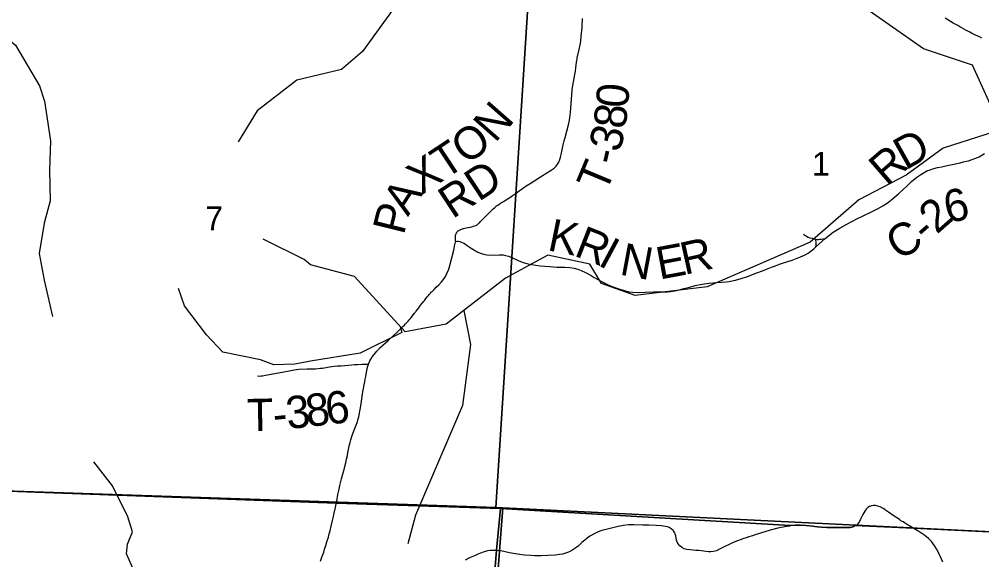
# Model space of a CAD drawing. Extents: x 0 to 34, y 0 to 22.
# Drawn here: x 4.109 to 5.797, y 15.893 to 16.841 of the extents above; entities that cross this region are included whole.
import ezdxf

# ---------------------------------------------------------------- set-up
doc = ezdxf.new("R2010")
doc.units = 0
for name, color, linetype in [('Default', 7, 'Continuous'), ('GM_X_County_Road', 7, 'Continuous'), ('GM_X_County_Road_Text', 7, 'Continuous'), ('GM_X_Minor_River', 7, 'Continuous'), ('GM_X_Section', 7, 'Continuous'), ('GM_X_Section_Text', 7, 'Continuous'), ('GM_X_Township_Road', 7, 'Continuous'), ('GM_X_Township_Road_Text', 7, 'Continuous')]:
    doc.layers.add(name, color=color, linetype=linetype)

msp = doc.modelspace()

# ---------------------------------------------------------------- linework, layer by layer
at = {"layer": 'Default'}
for points in [[(3.9292, 16.0191), (4.6644, 15.9921), (4.9525, 15.9829), (5.4606, 15.953), (5.4699, 15.9536), (5.4787, 15.9537), (5.4884, 15.9532), (5.5007, 15.9519), (5.5038, 15.9516), (5.5088, 15.951), (5.5156, 15.9503), (5.5249, 15.9499), (5.5387, 15.9494), (5.5476, 15.9495), (5.5597, 15.9496), (5.5657, 15.9498), (5.5704, 15.951), (5.5736, 15.9525), (5.5744, 15.953), (5.6773, 15.9486), (6.0035, 15.9327), (6.0487, 16.67), (6.0603, 16.8624), (6.127, 17.9511)], [(6.0035, 15.9327), (5.6773, 15.9486), (5.5744, 15.953), (5.5736, 15.9525), (5.5704, 15.951), (5.5657, 15.9498), (5.5597, 15.9496), (5.5476, 15.9495), (5.5387, 15.9494), (5.5249, 15.9499), (5.5156, 15.9503), (5.5088, 15.951), (5.5038, 15.9516), (5.5007, 15.9519), (5.4884, 15.9532), (5.4787, 15.9537), (5.4699, 15.9536), (5.4606, 15.953), (4.9525, 15.9829), (4.9458, 15.9099), (4.8987, 15.3279)]]:
    msp.add_lwpolyline(points, dxfattribs=at)
msp.add_lwpolyline([(2.1, 16.1239), (2.1, 14.1), (4.8164, 14.1), (4.8734, 15.0246), (4.8987, 15.3279), (4.9458, 15.9099), (4.9525, 15.9829), (4.6644, 15.9921), (3.9292, 16.0191), (3.6368, 16.0331), (2.1721, 16.1195)], close=True, dxfattribs=at)
at = {"layer": 'GM_X_County_Road'}
for points in [[(5.7969, 16.8083), (5.7925, 16.8105), (5.7858, 16.8138), (5.7836, 16.8149), (5.7788, 16.8173), (5.7761, 16.8187), (5.7724, 16.8205), (5.7686, 16.8225), (5.7609, 16.8267), (5.7583, 16.8282), (5.7547, 16.8303), (5.751, 16.8323), (5.7466, 16.8346), (5.7324, 16.8435)], [(5.506, 16.4421), (5.5224, 16.4566), (5.5363, 16.4676), (5.5467, 16.4745), (5.5601, 16.4821), (5.5778, 16.4913), (5.6024, 16.5032), (5.6141, 16.509), (5.6233, 16.5142), (5.6306, 16.519), (5.6395, 16.5258), (5.6514, 16.5359), (5.6664, 16.5499), (5.6737, 16.5566), (5.6827, 16.5642), (5.6896, 16.5692), (5.6955, 16.5728), (5.7007, 16.5754), (5.7064, 16.5775), (5.7129, 16.5796), (5.7193, 16.5811), (5.727, 16.5827), (5.7363, 16.5846), (5.7589, 16.5897), (5.7649, 16.5911), (5.7698, 16.5922), (5.7734, 16.5933), (5.7779, 16.5949), (5.7845, 16.5972), (5.792, 16.6003), (5.8018, 16.6056)], [(4.7214, 16.2365), (4.7225, 16.2391), (4.7239, 16.2423), (4.7252, 16.245), (4.7277, 16.2492), (4.731, 16.2534), (4.7361, 16.2592), (4.7413, 16.2647), (4.756, 16.2779), (4.7647, 16.2859), (4.7723, 16.293), (4.778, 16.2986), (4.7816, 16.3023), (4.7842, 16.3048), (4.7858, 16.3065), (4.7874, 16.3082), (4.789, 16.3098), (4.7901, 16.3111), (4.7909, 16.312), (4.7928, 16.3142), (4.7947, 16.3166), (4.7966, 16.3189), (4.7996, 16.3227), (4.8019, 16.3256), (4.8029, 16.3271), (4.8037, 16.328), (4.8049, 16.3294), (4.8093, 16.3351), (4.8126, 16.3395), (4.8156, 16.3432), (4.8167, 16.3446), (4.8178, 16.346), (4.8185, 16.3469), (4.8198, 16.3488), (4.8219, 16.3514), (4.8242, 16.3542), (4.8254, 16.3556), (4.8265, 16.357), (4.8278, 16.3583), (4.829, 16.3597), (4.8302, 16.361), (4.8319, 16.3629), (4.8327, 16.3637), (4.8345, 16.3655), (4.8362, 16.3672), (4.84, 16.3712), (4.8446, 16.3757), (4.8492, 16.3807), (4.8528, 16.385), (4.8562, 16.3902), (4.8595, 16.3967), (4.862, 16.4028), (4.864, 16.4092), (4.8676, 16.423), (4.8708, 16.436), (4.8726, 16.4463), (4.873, 16.4488), (4.8737, 16.4503), (4.8743, 16.4508)], [(4.8743, 16.4508), (4.875, 16.4514), (4.8765, 16.4519), (4.8785, 16.4522), (4.8817, 16.4516), (4.8853, 16.45), (4.8885, 16.4483), (4.8911, 16.4467), (4.8943, 16.4446), (4.8976, 16.4424), (4.9015, 16.44), (4.9043, 16.4383), (4.909, 16.4353), (4.9111, 16.434), (4.9133, 16.4328), (4.9179, 16.4309), (4.9232, 16.4292), (4.9286, 16.4282), (4.9352, 16.4278), (4.9507, 16.4282), (4.9572, 16.4279), (4.9618, 16.4272), (4.9669, 16.4257), (4.9752, 16.4222), (4.9801, 16.4198), (4.9849, 16.4178), (4.9923, 16.4147), (4.9988, 16.4128), (5.0035, 16.4118), (5.0074, 16.411), (5.015, 16.4098), (5.0226, 16.4089), (5.0307, 16.408), (5.039, 16.4074), (5.0455, 16.4069), (5.0517, 16.4067), (5.0576, 16.4065), (5.0655, 16.4063), (5.0746, 16.4056), (5.0818, 16.4047), (5.0882, 16.403), (5.0945, 16.4006), (5.1017, 16.3972), (5.1115, 16.3917), (5.1173, 16.3883), (5.1244, 16.3842), (5.1308, 16.3806), (5.1394, 16.3765), (5.1468, 16.3733), (5.1565, 16.3696), (5.1618, 16.368), (5.168, 16.3661), (5.1777, 16.3634), (5.1845, 16.3625), (5.1945, 16.3622), (5.2063, 16.3626), (5.2212, 16.3632), (5.2267, 16.3634), (5.2379, 16.3631), (5.2454, 16.3633), (5.2516, 16.3639), (5.2614, 16.3657), (5.2747, 16.369), (5.2795, 16.3703), (5.2864, 16.3721), (5.2944, 16.3743), (5.3065, 16.3768), (5.3185, 16.3785), (5.3309, 16.3794), (5.3416, 16.3802), (5.3484, 16.3808), (5.3538, 16.3813), (5.3613, 16.383), (5.3647, 16.3837), (5.3751, 16.3867), (5.3861, 16.3903), (5.4025, 16.3964), (5.4122, 16.4001), (5.4222, 16.404), (5.4281, 16.4062), (5.4352, 16.4089), (5.442, 16.4115), (5.4489, 16.4138), (5.4547, 16.4158), (5.4644, 16.419), (5.4787, 16.4243), (5.4859, 16.4274), (5.4923, 16.4312), (5.4972, 16.4347), (5.503, 16.4394), (5.506, 16.4421)], [(4.6646, 15.9915), (4.6655, 15.9958), (4.6677, 16.0073), (4.6688, 16.0125), (4.6697, 16.0172), (4.6709, 16.0231), (4.672, 16.0281), (4.6738, 16.0349), (4.6755, 16.0413), (4.6766, 16.0455), (4.6784, 16.0517), (4.6798, 16.0569), (4.6814, 16.0633), (4.6829, 16.0696), (4.6843, 16.0763), (4.6853, 16.0814), (4.6864, 16.0867), (4.6875, 16.0921), (4.6882, 16.0956), (4.6889, 16.0988), (4.6902, 16.1035), (4.6913, 16.1077), (4.6925, 16.1111), (4.6937, 16.1147), (4.696, 16.1206), (4.6979, 16.1254), (4.7004, 16.1312), (4.7017, 16.1348), (4.7028, 16.1386), (4.7042, 16.1437), (4.7055, 16.15), (4.7061, 16.1539), (4.7066, 16.157), (4.7082, 16.1667), (4.711, 16.1843), (4.7139, 16.1998), (4.7148, 16.2052), (4.7155, 16.2101), (4.7165, 16.2148), (4.7172, 16.219), (4.7182, 16.2247), (4.7191, 16.2289), (4.7202, 16.2328), (4.7214, 16.2365)], [(4.6369, 15.8906), (4.6383, 15.894), (4.6397, 15.8978), (4.6407, 15.9004), (4.6428, 15.9066), (4.6444, 15.9116), (4.6465, 15.9183), (4.6483, 15.9245), (4.6509, 15.933), (4.6525, 15.9388), (4.6539, 15.9438), (4.6559, 15.9522), (4.6582, 15.9619), (4.6592, 15.9668), (4.661, 15.9747), (4.6633, 15.985), (4.6646, 15.9915)], [(5.6768, 15.9485), (5.6747, 15.9498), (5.6645, 15.9558), (5.661, 15.9579), (5.6587, 15.9594), (5.6551, 15.9614), (5.6529, 15.963), (5.6505, 15.9647), (5.6429, 15.9697), (5.633, 15.9768), (5.6282, 15.9801), (5.6267, 15.9811), (5.624, 15.9828), (5.6185, 15.9857), (5.6144, 15.9873), (5.6106, 15.9881), (5.6068, 15.9881), (5.6036, 15.9876), (5.6001, 15.9864), (5.5971, 15.9847), (5.594, 15.9817), (5.5915, 15.9782), (5.5884, 15.9725), (5.5849, 15.9655), (5.5822, 15.9601), (5.5789, 15.9556), (5.5762, 15.9534), (5.5746, 15.9525), (5.5738, 15.952)], [(5.4596, 15.9523), (5.4511, 15.9511), (5.4393, 15.9486), (5.4281, 15.9458), (5.4178, 15.9425), (5.3995, 15.9368), (5.3948, 15.9353), (5.3924, 15.9345), (5.3883, 15.9331), (5.3836, 15.9316), (5.3795, 15.9301), (5.3637, 15.9244), (5.3564, 15.9212), (5.3512, 15.9188), (5.3483, 15.9174), (5.3425, 15.9146), (5.3367, 15.9115), (5.3314, 15.9089), (5.3265, 15.9074), (5.3217, 15.9069), (5.3174, 15.907), (5.3128, 15.9075), (5.3094, 15.9079), (5.3047, 15.9086), (5.3004, 15.9093), (5.2956, 15.9095), (5.2908, 15.9097), (5.2849, 15.9103), (5.2798, 15.9111), (5.2751, 15.9123), (5.2708, 15.9144), (5.2672, 15.9176), (5.2643, 15.9213), (5.2626, 15.9242), (5.2614, 15.9275), (5.2601, 15.9353), (5.2593, 15.9377), (5.2583, 15.9405), (5.2573, 15.9422), (5.2562, 15.9436), (5.255, 15.9451), (5.2521, 15.9476), (5.2483, 15.9498), (5.2459, 15.9508), (5.2423, 15.9517), (5.2353, 15.9527), (5.2255, 15.9532), (5.2129, 15.9537), (5.2023, 15.954), (5.1868, 15.9543), (5.1774, 15.9542), (5.1687, 15.9532), (5.159, 15.9514), (5.1425, 15.9476), (5.1303, 15.9442), (5.1272, 15.9431), (5.1226, 15.9413), (5.1171, 15.9385), (5.1095, 15.9342), (5.1049, 15.9309), (5.1007, 15.9277), (5.0956, 15.9233), (5.0925, 15.9205), (5.0888, 15.9171), (5.0847, 15.9138), (5.0778, 15.9091), (5.0718, 15.9063), (5.0667, 15.9044), (5.0615, 15.9031), (5.0561, 15.9023), (5.0494, 15.9014), (5.0357, 15.9004), (5.0238, 15.9001), (5.0128, 15.9), (5.0062, 15.9003), (4.9948, 15.9012), (4.9827, 15.9029), (4.9688, 15.9055), (4.9609, 15.9071), (4.9531, 15.9086), (4.946, 15.9094)], [(5.5738, 15.952), (5.5706, 15.9505), (5.5659, 15.9493), (5.5599, 15.9491), (5.5479, 15.949), (5.5389, 15.9489), (5.5251, 15.9494), (5.5158, 15.9498), (5.509, 15.9504), (5.504, 15.9511), (5.5009, 15.9514), (5.4886, 15.9527), (5.4789, 15.9532), (5.4701, 15.953), (5.4608, 15.9525), (5.4596, 15.9523)], [(5.7282, 15.8887), (5.7241, 15.8984), (5.7226, 15.9015), (5.7203, 15.9072), (5.7174, 15.9124), (5.7145, 15.917), (5.7118, 15.9209), (5.7084, 15.925), (5.7035, 15.9302), (5.6968, 15.9357), (5.6863, 15.9426), (5.6775, 15.9481), (5.6768, 15.9485)], [(4.946, 15.9094), (4.9445, 15.9095), (4.9389, 15.9096), (4.9347, 15.9093), (4.9302, 15.9085), (4.9243, 15.907), (4.9175, 15.9046), (4.9117, 15.9021), (4.907, 15.9002), (4.8984, 15.8966), (4.8906, 15.8926)]]:
    msp.add_lwpolyline(points, dxfattribs=at)
at = {"layer": 'GM_X_Minor_River'}
for points in [[(5.8267, 16.659), (5.7806, 16.7611), (5.6944, 16.7896), (5.5932, 16.8604), (5.56, 16.9319), (5.5274, 16.9877), (5.4057, 17.0349), (5.2859, 17.0482), (5.2231, 17.0355), (5.2102, 17.0327), (5.1385, 16.9998), (5.0417, 17.0267), (4.9517, 17.0338), (4.8632, 16.9514), (4.7891, 16.8935), (4.7108, 16.785), (4.674, 16.7535), (4.5957, 16.7346), (4.5258, 16.6805), (4.4927, 16.6266)], [(4.0043, 16.8113), (4.0456, 16.8229), (4.0899, 16.8058), (4.102, 16.796), (4.1441, 16.7249), (4.1532, 16.6975), (4.1638, 16.628), (4.1618, 16.5766), (4.1633, 16.5226), (4.1527, 16.4835), (4.144, 16.4302), (4.1523, 16.3835), (4.167, 16.32)], [(5.8331, 16.6488), (5.7289, 16.6153), (5.6643, 16.5676), (5.5809, 16.5244), (5.4957, 16.4504), (5.3153, 16.3717), (5.1891, 16.3569), (5.13, 16.378), (5.1094, 16.4116), (5.0356, 16.4277), (4.9613, 16.3871), (4.8576, 16.3065), (4.7856, 16.293), (4.6967, 16.3901), (4.6197, 16.4107), (4.6082, 16.42), (4.5364, 16.4558)], [(4.7768, 16.3026), (4.7799, 16.2917), (4.7069, 16.2558), (4.6193, 16.2415), (4.5919, 16.2365), (4.555, 16.2351), (4.532, 16.2438), (4.4661, 16.2572), (4.4369, 16.288), (4.3988, 16.3387), (4.3879, 16.3689)], [(4.8882, 16.3303), (4.9002, 16.2708), (4.8864, 16.164), (4.8039, 15.9716), (4.7905, 15.921)], [(4.3106, 15.873), (4.2969, 15.9034), (4.2988, 15.9205), (4.3072, 15.9418), (4.2992, 15.9684), (4.2723, 16.0228), (4.2394, 16.0649)]]:
    msp.add_lwpolyline(points, dxfattribs=at)
at = {"layer": 'GM_X_Section'}
for points in [[(5.0081, 16.9831), (4.9447, 15.9846), (3.8924, 16.0203), (3.9555, 17.0086), (4.4681, 17.0085)], [(6.0674, 16.9363), (6.0506, 16.6748), (6.0049, 15.9328), (4.9568, 15.9843), (4.9447, 15.9846), (5.0081, 16.9831)], [(3.8924, 16.0203), (4.9447, 15.9846), (4.9568, 15.9843), (4.8777, 14.9601), (3.8368, 15.0128)], [(4.9568, 15.9843), (6.0049, 15.9328), (5.9932, 15.6936), (5.9754, 15.4391), (5.9587, 15.1787), (5.9407, 14.9107), (5.9405, 14.9074), (4.8777, 14.9601)]]:
    msp.add_lwpolyline(points, close=True, dxfattribs=at)
at = {"layer": 'GM_X_Township_Road'}
for points in [[(4.8743, 16.4508), (4.8741, 16.4535), (4.8737, 16.4591), (4.8736, 16.4609), (4.8738, 16.462), (4.8741, 16.4632), (4.8744, 16.4642), (4.8748, 16.465), (4.8764, 16.4677), (4.8788, 16.4701), (4.8818, 16.472), (4.8846, 16.4732), (4.8881, 16.4744), (4.8928, 16.4755), (4.8993, 16.4767), (4.9027, 16.4775), (4.9054, 16.4781), (4.9095, 16.4796), (4.9118, 16.4807), (4.9138, 16.4822), (4.9149, 16.4835), (4.9157, 16.4843), (4.9173, 16.4861), (4.921, 16.4902), (4.924, 16.4932), (4.9258, 16.495), (4.9293, 16.4984), (4.9315, 16.5006), (4.9396, 16.5083), (4.9428, 16.5112), (4.945, 16.5132), (4.946, 16.5139), (4.9479, 16.5152), (4.95, 16.5164), (4.953, 16.5185), (4.9581, 16.5217), (4.9597, 16.5226), (4.9676, 16.5275), (4.9732, 16.5314), (4.9782, 16.535), (4.9802, 16.5364), (4.9857, 16.5403), (4.989, 16.5428), (4.9913, 16.5447), (4.9979, 16.5491), (5.0045, 16.5534), (5.0128, 16.5586), (5.023, 16.5649), (5.0339, 16.5719), (5.0418, 16.5769), (5.047, 16.5804), (5.0502, 16.5834), (5.0529, 16.5869), (5.0551, 16.5908), (5.057, 16.5954), (5.0581, 16.5996), (5.0592, 16.6039), (5.0611, 16.6126), (5.0629, 16.6209), (5.0642, 16.6283), (5.0661, 16.6341), (5.0689, 16.6449), (5.0724, 16.6588), (5.0736, 16.6646), (5.0744, 16.6685), (5.0751, 16.6734), (5.0757, 16.6777), (5.0763, 16.6858), (5.0777, 16.7086), (5.0786, 16.7178), (5.0796, 16.7252), (5.083, 16.7446), (5.084, 16.7504), (5.085, 16.7562), (5.0863, 16.7662), (5.0867, 16.7688), (5.0871, 16.7716), (5.0875, 16.7736), (5.0903, 16.7861), (5.0928, 16.7989), (5.0935, 16.8041), (5.0951, 16.8175), (5.0955, 16.8201), (5.0956, 16.823), (5.0957, 16.826), (5.0958, 16.8295), (5.096, 16.8332), (5.0963, 16.8382), (5.0967, 16.8425)], [(5.4842, 16.4644), (5.487, 16.4623), (5.4895, 16.4608), (5.4925, 16.4592), (5.4955, 16.4582), (5.4992, 16.4572), (5.5027, 16.4563), (5.5049, 16.4558), (5.5076, 16.4552), (5.5102, 16.4551), (5.5125, 16.4553), (5.5153, 16.4556), (5.5182, 16.456), (5.5224, 16.4566)], [(5.506, 16.4421), (5.5062, 16.445), (5.5064, 16.4476), (5.5064, 16.4494), (5.5063, 16.451), (5.5058, 16.4533), (5.5049, 16.4558)], [(4.5267, 16.2158), (4.5305, 16.2155), (4.533, 16.2157), (4.5354, 16.2159), (4.5409, 16.2167), (4.5568, 16.2196), (4.5726, 16.2229), (4.5849, 16.2253), (4.5909, 16.2264), (4.599, 16.2273), (4.6138, 16.2278), (4.6207, 16.2279), (4.6286, 16.2283), (4.633, 16.2287), (4.6372, 16.2291), (4.6405, 16.2294), (4.6436, 16.2299), (4.6472, 16.2305), (4.6496, 16.2309), (4.653, 16.2315), (4.657, 16.2321), (4.6608, 16.2325), (4.6669, 16.2331), (4.6731, 16.2335), (4.6864, 16.2347), (4.6918, 16.2351), (4.6969, 16.2354), (4.7023, 16.2357), (4.7101, 16.2362), (4.7165, 16.2365), (4.7214, 16.2365)]]:
    msp.add_lwpolyline(points, dxfattribs=at)

# ---------------------------------------------------------------- texts
at = {"layer": 'GM_X_County_Road_Text'}
for s, rotation, p in [('D', 29.228, (5.663, 16.5759)), ('R', 40.8386, (5.6302, 16.5471)), ('6', 13.3433, (5.7376, 16.4828)), ('2', 41.2716, (5.7178, 16.4631)), ('K', 348.4693, (5.0334, 16.4365)), ('R', 338.6244, (5.0799, 16.4272)), ('C', 30.7877, (5.6509, 16.417)), ('-', 41.4489, (5.7003, 16.4477)), ('I', 331.7904, (5.1218, 16.4109)), ('N', 349.4188, (5.16, 16.3937)), ('E', 10.5457, (5.2315, 16.3845)), ('R', 12.5034, (5.2753, 16.3927))]:
    msp.add_text(s, height=0.0568, rotation=rotation, dxfattribs=at).set_placement(p)
at = {"layer": 'GM_X_Section_Text'}
for s, p in [('1', (5.4991, 16.5669)), ('7', (4.435, 16.4712))]:
    msp.add_text(s, height=0.0419, rotation=0, dxfattribs=at).set_placement(p)
at = {"layer": 'GM_X_Township_Road_Text'}
for s, height, rotation, p in [('0', 0.0568, 85.0182, (5.1761, 16.6844)), ('N', 0.0568, 48.6455, (4.9432, 16.6233)), ('8', 0.0568, 83.1109, (5.1717, 16.6476)), ('O', 0.0568, 36.3398, (4.8931, 16.5847)), ('3', 0.0568, 76.2446, (5.162, 16.6063)), ('T', 0.0568, 33.3311, (4.855, 16.5595)), ('-', 0.0568, 76.9909, (5.1568, 16.5838)), ('X', 0.0568, 33.7896, (4.8135, 16.5318)), ('T', 0.0568, 67.3056, (5.1372, 16.5346)), ('RD', 0.05682, 33.4162, (4.8686, 16.4903)), ('A', 0.0568, 56.9707, (4.7905, 16.4942)), ('P', 0.0568, 76.0358, (4.7832, 16.4615)), ('6', 0.0568, 6.5027, (4.6487, 16.1299)), ('T', 0.0568, 1.2332, (4.5086, 16.1184)), ('3', 0.0568, 6.3814, (4.5795, 16.1221)), ('8', 0.0568, 6.4735, (4.6141, 16.126)), ('-', 0.0568, 5.978, (4.5561, 16.1196))]:
    msp.add_text(s, height=height, rotation=rotation, dxfattribs=at).set_placement(p)

doc.saveas('drawing.dxf')
